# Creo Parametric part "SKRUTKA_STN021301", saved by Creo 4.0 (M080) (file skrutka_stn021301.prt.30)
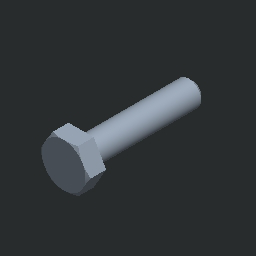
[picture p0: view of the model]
Units: Custom; MM, KILOGRAM, SECS
Materials in the file: OCEL_N

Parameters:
  MFG_WP_MATERIAL = "OCEL"
  NAZOV = "SKRUTKA_STN021301"
  NORMA = "STN 02 1301"
  PTC_MATERIAL_NAME = "OCEL_N"

Other parameters: HMOTNOST, HUSTOTA, D14

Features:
  1. datum plane "DTM1"
  2. protrusion
  3. datum plane "DTM3"
  4. cut
  5. chamfer
  6. round
  7. datum plane "DTM4"
  8. datum plane "DTM5"

Other named items: BLIND

Layers: 1, 2, 3, 4, 5, 6, 7, 8, 9, 10, 11, 12, 13, 14, 15, 16, 17, 18, 19, 20, 21, 22, 23, 24, 25, 26, 27, 28, 29, 30, 31, 32

Family table entries: GENERIC, SKRUKA_M5, SKRUTKA_STN021301, value(d_val), 2/ , value(i_val), SKRUKA_M6, SKRUTKA_STN021301, 2/$, SKRUKA_M8, SKRUTKA_STN021301, !/ , 2/*, SKRUKA_M10, SKRUTKA_STN021301, !/$, 2/0, SKRUKA_M12, SKRUTKA_STN021301, !/(, 2/ , 2/2, SKRUKA_M16, SKRUTKA_STN021301, !/0, 2/$, 2/8, SKRUKA_M20, SKRUTKA_STN021301, !/4, 2/*, 2/>, SKRUKA_M22, SKRUTKA_STN021301, !/6, 2/,, 2/A, SKRUKA_M24, SKRUTKA_STN021301, !/8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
